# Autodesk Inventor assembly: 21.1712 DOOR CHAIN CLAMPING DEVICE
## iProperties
Created: 2007-05
Part Number: 21.1712 DOOR CHAIN CLAMPING DEVICE
Document SubType Name: Assembly
Designer: Andy Moles
Mass: 65.0185 g
Surface Area: 65.3078 cm^2
Volume: 8.27931 cm^3
Density: 7.85313 g/cm^3
Author: Andy Moles
